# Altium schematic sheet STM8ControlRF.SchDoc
size A
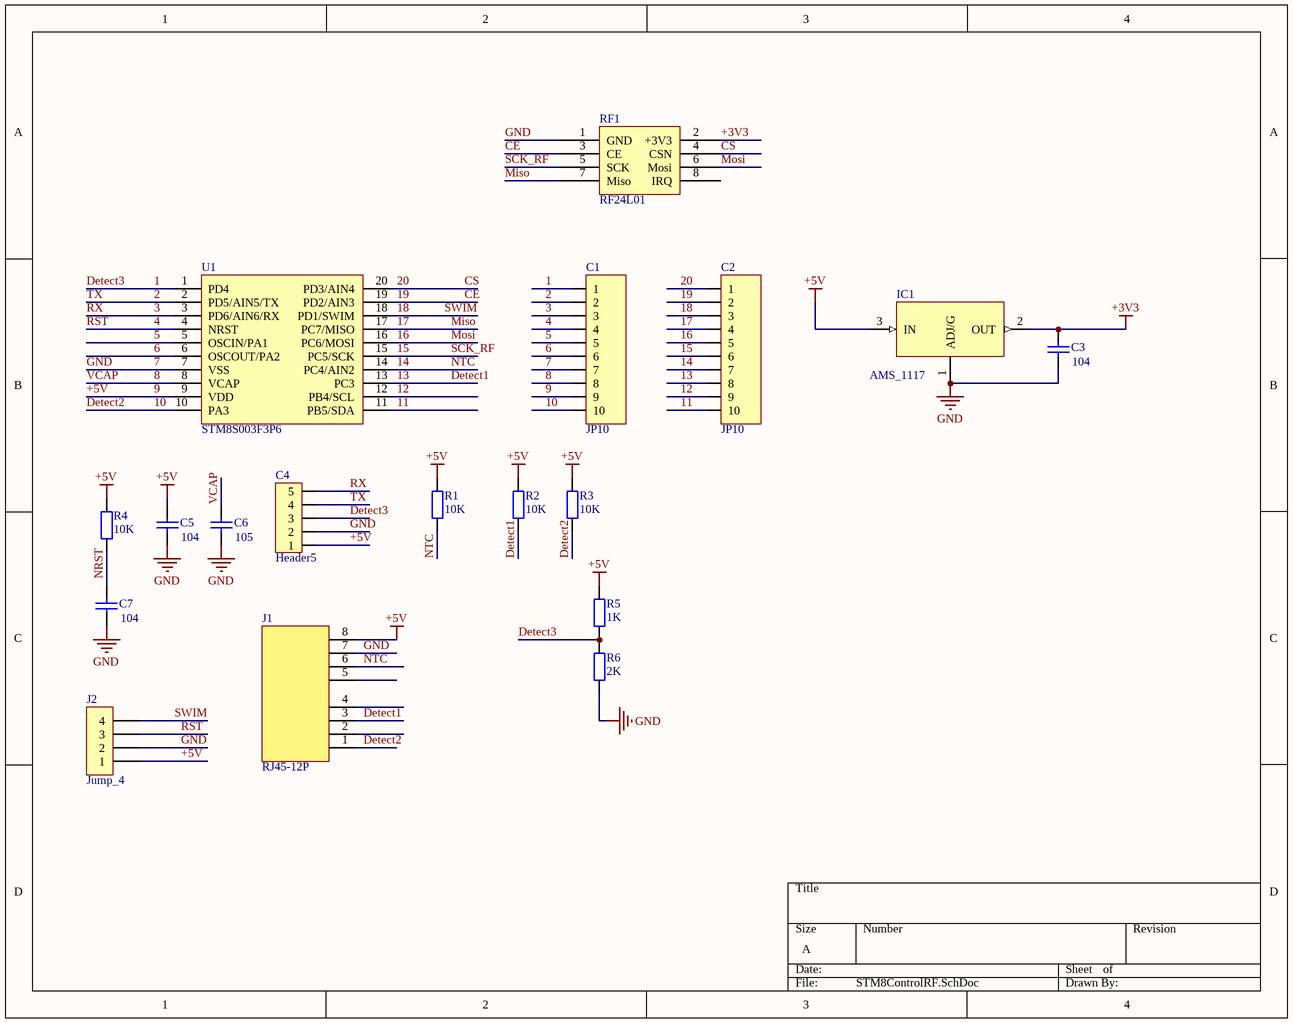
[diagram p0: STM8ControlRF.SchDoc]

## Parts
C1  JP10  [JP10-C1T]
C2  JP10  [JP10-C1T]
C3  104  [C0805]
C4  Header5  [HDR5]
C5  104  [C0805]
C6  105  [C0805]
C7  104  [C0805]
IC1  AMS_1117  [SOT_223_2]
J1  RJ45-12P  [RJ45-8PIN_18MM_NO_TRANSFORMER]
J2  Jump_4  [Jump_4]
R1  10K  [RES-0805]
R2  10K  [RES-0805]
R3  10K  [RES-0805]
R4  10K  [RES-0805]
R5  1K  [RES-0805]
R6  2K  [RES-0805]
RF1  RF24L01  [RF24L01]
U1  STM8S003F3P6  [TSSOP20]

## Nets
7: C1.7 C3.1 C4.2 C5.1 C6.1 C7.1 IC1.1(ADJ/G) J1.7 J2.2 R6.1 RF1.1(GND) U1.7(VSS)  [also labelled GND]
+3V3: C3.2 IC1.2(OUT) RF1.2(+3V3)
+5V: C1.9 C4.1 C5.2 IC1.3(IN) J1.8 J2.1 R1.2 R2.2 R3.2 R4.2 R5.2 U1.9(VDD)  [also labelled 9]
1: C1.1 C4.3 R5.1 R6.2 U1.1(PD4)  [also labelled Detect3]
2: C1.2 C4.4 U1.2(PD5/AIN5/TX)  [also labelled TX]
3: C1.3 C4.5 U1.3(PD6/AIN6/RX)  [also labelled RX]
4: C1.4 J2.3 U1.4(NRST)  [also labelled RST]
5: C1.5 U1.5(OSCIN/PA1)
6: C1.6 U1.6(OSCOUT/PA2)
8: C1.8 C6.2 U1.8(VCAP)  [also labelled VCAP]
10: C1.10 J1.1 R3.1 U1.10(PA3)  [also labelled Detect2]
11: C2.10 U1.11(PB5/SDA)
12: C2.9 U1.12(PB4/SCL)
13: C2.8 J1.3 R2.1 U1.13(PC3)  [also labelled Detect1]
14: C2.7 J1.6 R1.1 U1.14(PC4/AIN2)  [also labelled NTC]
15: C2.6 RF1.5(SCK) U1.15(PC5/SCK)  [also labelled SCK_RF]
16: C2.5 RF1.6(Mosi) U1.16(PC6/MOSI)  [also labelled Mosi]
17: C2.4 RF1.7(Miso) U1.17(PC7/MISO)  [also labelled Miso]
18: C2.3 J2.4 U1.18(PD1/SWIM)  [also labelled SWIM]
19: C2.2 RF1.3(CE) U1.19(PD2/AIN3)  [also labelled CE]
20: C2.1 RF1.4(CSN) U1.20(PD3/AIN4)  [also labelled CS]
NRST: C7.2 R4.1

Not connected (* = marked no-connect by the designer): J1 2 4 5; RF1 8(IRQ)

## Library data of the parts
C1 C2 = JP10: WR-PHD 2.54 mm Angled Socket Header; Manufacturer: W¨¹rth Elektronik eiSos GmbH; partNo: 613010143121; ComponentLink1 Description: Manufacturer; ComponentLink2 Description: Datasheet; NoPins: 10
C3 C5-C7 = CapSMD: Capacitor; Value: 33p
C4 = Header5: Header IDC, 5 x 1 Pin Vertical 2.54mm Pitch (Non-Boxed, Male); Manufacturer: W¨¹rth Elektronik eiSos GmbH; partNo: 613002143121; ComponentLink1 Description: Manufacturer; ComponentLink2 Description: Datasheet; NoPins: 02
IC1 = AMS_1117: IC Power
J1 = RJ45-12PIN_NO_TRANSFORMER: Solder: WAVE
R1-R4 R6 = RES: Resistor SMD; Value: 1K
R5 = RES: Resistor SMD
RF1 = RF24L01: Module RF24L01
